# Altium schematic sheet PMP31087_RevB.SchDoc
size 431 x 279 mm; Date: Not shown in title block; ApprovedBy: Not shown in title block; CheckedBy: Not shown in title block; Author: Not shown in title block; CompanyName: Not shown in title block; Engineer: Not shown in title block; Organization: Not shown in title block; Address1: Not shown in title block; Address2: Not shown in title block; Address3: Not shown in title block; Address4: Not shown in title block; DocumentNumber: 1; Revision: Use project parameter SCH_Rev; SheetNumber: 1; SheetTotal: 1; PageSetup: Record=PageOptions¦CenterHorizontal=True¦CenterVertical=True¦PrintScale=1.00¦XCorrection=1.00¦YCorrection=1.00¦PrintKind=0¦BorderSize=5000000¦LeftOffset=0¦BottomOffset=0¦Orientation=2¦PaperLength=1000¦PaperWidth=1000¦Scale=100¦PaperSource=15¦PrintQuality=600¦MediaType=1¦DitherType=10¦PaperKind=Letter¦PrintScaleMode=1
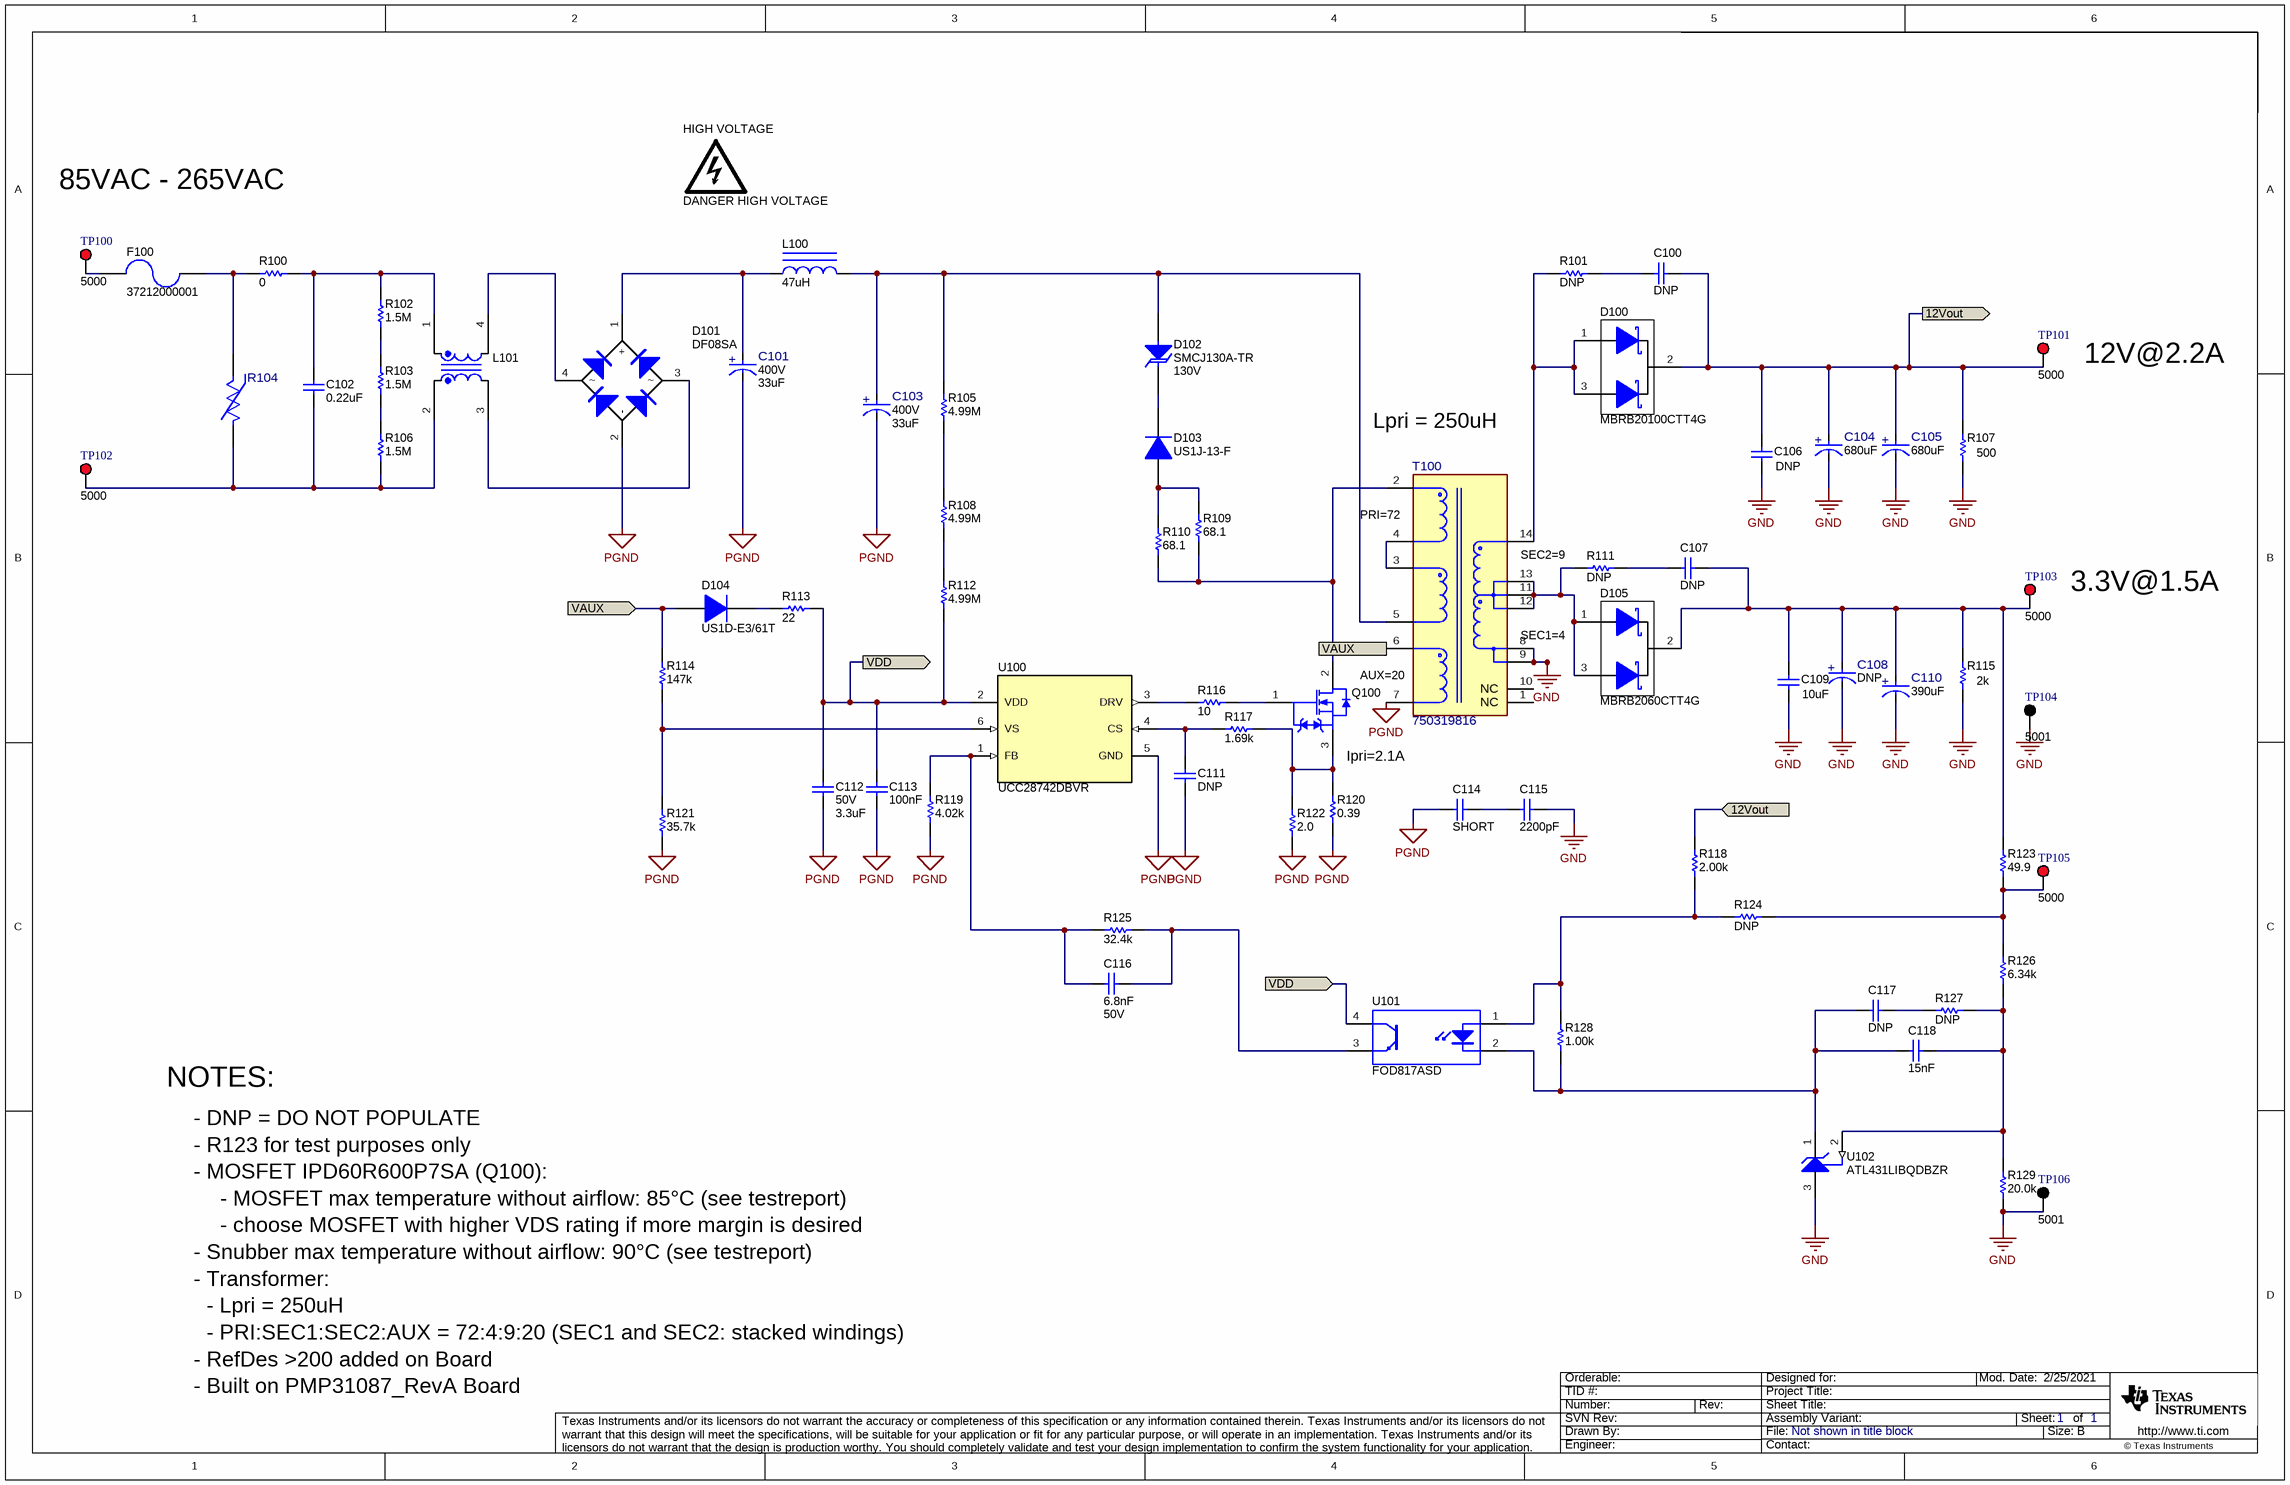
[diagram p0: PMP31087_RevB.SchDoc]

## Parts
C100  Cap_F: DNP  [0805_HV]  (hidden comment: GRM21AR72E102KW01D)
C101  VDC_V: 400V  ValueDisplayed: 33uF  [FP-860241381004_RADIAL-MFG]  (hidden comment: 860241381004)
C102  ValueDisplayed: 0.22uF  [WCAP-FTX2_1800x600x1150]  (hidden comment: 890324025027CS)
C103  VDC_V: 400V  ValueDisplayed: 33uF  [FP-860241381004_RADIAL-MFG]  (hidden comment: 860241381004)
C104  ValueDisplayed: 680uF  [FP-25ZL680MEFC10X20_RADIAL-MFG]  (hidden comment: 25ZL680MEFC10X20)
C105  ValueDisplayed: 680uF  [FP-25ZL680MEFC10X20_RADIAL-MFG]  (hidden comment: 25ZL680MEFC10X20)
C106  ValueDisplayed: DNP  [1210_200]  (hidden comment: GRM32RR71H105KA01L)
C107  Cap_F: DNP  [0805_HV]  (hidden comment: GRM21AR72E102KW01D)
C108  DNP  [FP-APXJ100ARA391MFA0G_SMD2-MFG]
C109  ValueDisplayed: 10uF  [1206]  (hidden comment: C3216X7R1A106M085AC)
C110  ValueDisplayed: 390uF  [FP-APXJ100ARA391MFA0G_SMD2-MFG]  (hidden comment: APXJ100ARA391MFA0G)
C111  Cap_F: DNP  [0603]
C112  VDC_V: 50V  ValueDisplayed: 3.3uF  [1206_190]  (hidden comment: C3216X7R1H335K160AC)
C113  Cap_F: 100nF  [0603]  (hidden comment: C1608X7R1H104K080AA)
C114  ValueDisplayed: SHORT  [C900_9x13]
C115  ValueDisplayed: 2200pF  [C900_9x13]  (hidden comment: C921U222MVVDBA7317)
C116  Cap_F: 6.8nF  VDC_V: 50V  [0603]  (hidden comment: C0603C682K5RACTU)
C117  Cap_F: DNP  [0603]
C118  Cap_F: 15nF  [0603]  (hidden comment: GRM188R71H153KA01D)
D100  MBRB20100CTT4G  [DDPAK]
D101  DF08SA  [DF-S]
D102  SMCJ130A-TR  value 130V  [SMC]
D103  US1J-13-F  [SMA]
D104  US1D-E3/61T  [SMA]
D105  MBRB2060CTT4G  [DDPAK]
F100  37212000001  [FUSE_372]
HIGH_VOLTAGE  DANGER HIGH VOLTAGE  [IEC_HighVoltage_Small]  (no BOM)
L100  ValueDisplayed: 47uH  [WE-TI_8075_STU]  (hidden comment: 744732470)
L101  744823220  [WE-CMB_M]  (value not drawn)
Q100  IPD60R600P7SAUMA1  [DPAK]  (value not drawn)
R100  ValueDisplayed: 0  [1210]  (hidden comment: CRCW12100000Z0EAHP)
R101  ValueDisplayed: DNP  [1206]  (hidden comment: CRCW120610R0FKEA)
R102  ValueDisplayed: 1.5M  [1206]  (hidden comment: CRCW12061M50JNEA)
R103  ValueDisplayed: 1.5M  [1206]  (hidden comment: CRCW12061M50JNEA)
R104  B72210S2271K101  [FP-B72210S2271K101_RADIAL-MFG]  (value not drawn)
R105  ValueDisplayed: 4.99M  [0603]  (hidden comment: CRCW06034M99FKEA)
R106  ValueDisplayed: 1.5M  [1206]  (hidden comment: CRCW12061M50JNEA)
R107  value 500  [1206]  (hidden comment: Used in BOM report)
R108  ValueDisplayed: 4.99M  [0603]  (hidden comment: CRCW06034M99FKEA)
R109  ValueDisplayed: 68.1  [1206]  (hidden comment: CRCW120668R1FKEA)
R110  ValueDisplayed: 68.1  [1206]  (hidden comment: CRCW120668R1FKEA)
R111  ValueDisplayed: DNP  [1206]  (hidden comment: CRCW120610R0FKEA)
R112  ValueDisplayed: 4.99M  [0603]  (hidden comment: CRCW06034M99FKEA)
R113  ValueDisplayed: 22  [1206]  (hidden comment: CRCW120622R0JNEA)
R114  ValueDisplayed: 147k  [0603]  (hidden comment: CRCW0603147KFKEA)
R115  value 2k  [1206]  (hidden comment: Used in BOM report)
R116  ValueDisplayed: 10  [0805_HV]  (hidden comment: CRCW080510R0JNEA)
R117  ValueDisplayed: 1.69k  [0603]  (hidden comment: CRCW06031K69FKEA)
R118  ValueDisplayed: 2.00k  [0805_HV]  (hidden comment: CRCW08052K00FKEA)
R119  ValueDisplayed: 4.02k  [0603]  (hidden comment: CRCW06034K02FKEA)
R120  ValueDisplayed: 0.39  [1206]  (hidden comment: ERJ-8RQFR39V)
R121  ValueDisplayed: 35.7k  [0603]  (hidden comment: CRCW060335K7FKEA)
R122  ValueDisplayed: 2.0  [0805_HV]  (hidden comment: ERJ-6GEYJ2R0V)
R123  ValueDisplayed: 49.9  [0603]  (hidden comment: CRCW060349R9FKEA)
R124  ValueDisplayed: DNP  [0603]  (hidden comment: CRCW06031K00FKEA)
R125  ValueDisplayed: 32.4k  [0603]  (hidden comment: CRCW060332K4FKEA)
R126  ValueDisplayed: 6.34k  [0603]  (hidden comment: RC0603FR-076K34L)
R127  ValueDisplayed: DNP  [0603]  (hidden comment: CRCW06034K02FKEA)
R128  ValueDisplayed: 1.00k  [0603]  (hidden comment: CRCW06031K00FKEA)
R129  ValueDisplayed: 20.0k  [0603]  (hidden comment: CRCW060320K0FKEA)
T100  750319816  [FP-750319816_PTH_TRANSFORMER_32MM25_27MM05-MFG]
TP100  5000  [Keystone5000]
TP101  5000  [Keystone5000]
TP102  5000  [Keystone5000]
TP103  5000  [Keystone5000]
TP104  5001  [Keystone5001]
TP105  5000  [Keystone5000]
TP106  5001  [Keystone5001]
U100  UCC28742DBVR  [DBV0006A_N]
U101  FOD817ASD  [N04C]
U102  ATL431LIBQDBZR  [DBZ0003A_N]

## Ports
12Vout (in), 12Vout (out), VAUX (in), VAUX (out), VDD (in), VDD (out)

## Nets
GND: C104.1(CATHODE) C105.1(CATHODE) C106.2 C108.1(CATHODE) C109.2 C110.1(CATHODE) C115.1 R107.1 R115.1 R129.1 T100.8 T100.9 TP104.1 TP106.1 U102.3(ANODE)
PGND: C101.1(CATHODE) C103.1(CATHODE) C111.2 C112.2 C113.2 C114.2 D101.2(-) R119.1 R120.1 R121.1 R122.1 T100.7 U100.5(GND)
12Vout: C100.1 C104.2(ANODE) C105.2(ANODE) C106.1 D100.2(K) R107.2 R118.2 TP101.1 ; port 12Vout
VAUX: D104.2(A) R114.2 T100.6 ; port VAUX
VDD: C112.1 C113.1 R112.1 R113.2 U100.2(VDD) U101.4(C) ; port VDD
NetC100_2: C100.2 R101.2
NetC101_2: C101.2(ANODE) D101.1(+) L100.1
NetC102_1: C102.1 L101.1 R100.2 R102.2
NetC102_2: C102.2 L101.2 R104.1 R106.1 TP102.1
NetC103_2: C103.2(ANODE) D102.2(A) L100.2 R105.2 T100.5
NetC107_1: C107.1 C108.2(ANODE) C109.1 C110.2(ANODE) D105.2(K) R115.2 R123.2 TP103.1
NetC107_2: C107.2 R111.2
NetC111_1: C111.1 R117.1 U100.4(CS)
NetC114_1: C114.1 C115.2
NetC116_1: C116.1 R125.2 U101.3(E)
NetC116_2: C116.2 R119.2 R125.1 U100.1(FB)
NetC117_1: C117.1 C118.2 R128.1 U101.2(K) U102.1(CATHODE)
NetC117_2: C117.2 R127.2
NetC118_1: C118.1 R126.1 R127.1 R129.2 U102.2(REF)
NetD100_1: D100.1(A) D100.3(A) R101.1 T100.14
NetD101_3: D101.3 L101.3
NetD101_4: D101.4 L101.4
NetD102_1: D102.1(K) D103.1(K)
NetD103_2: D103.2(A) R109.2 R110.2
NetD104_1: D104.1(K) R113.1
NetD105_1: D105.1(A) D105.3(A) R111.1 T100.11 T100.12 T100.13
NetF100_1: F100.1 R100.1 R104.2
NetF100_2: F100.2 TP100.1
NetQ100_1: Q100.1(G) R116.2
NetQ100_2: Q100.2(D) R109.1 R110.1 T100.2
NetQ100_3: Q100.3(S) R117.2 R120.2 R122.2
NetR102_1: R102.1 R103.2
NetR103_1: R103.1 R106.2
NetR105_1: R105.1 R108.2
NetR108_1: R108.1 R112.2
NetR114_1: R114.1 R121.2 U100.6(VS)
NetR116_1: R116.1 U100.3(DRV)
NetR118_1: R118.1 R124.1 R128.2 U101.1(A)
NetR123_1: R123.1 R124.2 R126.2 TP105.1
NetT100_3: T100.3 T100.4

Not connected (* = marked no-connect by the designer): T100 1(NC) 10(NC)

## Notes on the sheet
- 85VAC - 265VAC
- (near TP101) 12V@2.2A
- Lpri = 250uH
- (near T100) PRI=72
- (near T100) SEC2=9
- (near T100) SEC1=4
- (near TP103) 3.3V@1.5A
- AUX=20
- Ipri=2.1A
- NOTES:
- - DNP = DO NOT POPULATE
- - R123 for test purposes only
- - MOSFET IPD60R600P7SA (Q100):
- - choose MOSFET with higher VDS rating if more margin is desired
- - MOSFET max temperature without airflow: 85°C (see testreport)
- - Transformer:
- - Snubber max temperature without airflow: 90°C (see testreport)
- - Lpri = 250uH
- - RefDes >200 added on Board
- - PRI:SEC1:SEC2:AUX = 72:4:9:20 (SEC1 and SEC2: stacked windings)
- - Built on PMP31087_RevA Board

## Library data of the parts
C100 C107 = CMP-0008251-1: CAP, CERM, 1000 pF, 250 V, +/- 10%, X7R, 0805; Manufacturer: MuRata; TaMin_C: -55°C; Polarized: N; SizeAreaWB_mm2: 6.75; Value1: Unknown; U/M: EA; Value: 1000pF; TaMax_C: 125°C; SizeZ_mm: 1.45; SizeX_mm: 2; SizeY_mm: 1.25; Cap_Case: 0805; Value2: 250V; SizeArea_mm2: 2.5; AEC Category: Q200
C101 C103 = CMP-0093307-1: 33 µF 400 V Aluminum Electrolytic Capacitors Radial, Can - 10000 Hrs @ 105°C; Manufacturer: Wurth Electronics; Value: 33µF; Tolerance_%: 20%; SizeZ_mm: 23mm; Leakage Current: 628uA; Life: 10000Hours; AEC Qualified: No; IRMS_A: 870mA
C102 = CMP-0012315-3: CAP, Film, 0.22 uF, 275 V, +/- 10%, TH; Manufacturer: Wurth Elektronik; TaMin_C: -40°C; Polarized: N; Value1: Unknown; Value: 0.22uF; TaMax_C: 105°C; Cap_Case: 18x11.5x6mm; Value2: 275V; Cap_F: 220nF; AEC Category: Q200
C104 C105 = CMP-0092158-1: Aluminum Electrolytic Capacitors Radial, Can - 4000 Hrs @ 105°C 680UF 25V; Manufacturer: Rubycon; Dissipation Factor: 14%; Value: 680µF; Leakage Current: 170uA; Life: 4000Hours; AEC Qualified: No; IRMS_A: 1.82A; Tolerance_%: 20%; SizeZ_mm: 22mm
C106 = CMP-0009251-1: CAP, CERM, 1 uF, +/- 10%, X7R, 1210; Manufacturer: MuRata; TaMin_C: -55°C; ESR_ohm: 3m; Polarized: N; SizeAreaWB_mm2: 14.7; Value1: 0.003 ohm; U/M: EA; Value: DNP; TaMax_C: 125°C; SizeZ_mm: 2; SizeX_mm: 3.2; SizeY_mm: 2.5; Cap_Case: 1210; SizeArea_mm2: 8
C108 = CMP-0092160-1: Capacitors Radial; SizeZ_mm: 10mm; Cap_F: 390µF; AEC Qualified: No; Leakage Current: 1950uA; Life: 15000Hours; Tolerance_%: 20%; Dissipation Factor: 12%; IRMS_A: 4A; Esr: 13m
C109 = CMP-0008688-1: CAP, CERM, 10 uF, 10 V, +/- 10%, X7R, 1206; Manufacturer: TDK; TaMin_C: -55°C; Polarized: N; SizeAreaWB_mm2: 10.92; Value1: Unknown; U/M: EA; Value: 10uF; TaMax_C: 125°C; SizeZ_mm: 1.35; SizeX_mm: 3.2; SizeY_mm: 1.6; Value2: 10V; SizeArea_mm2: 5.12; Cap_F: 10µF; AEC Category: Q200
C110 = CMP-0092160-1: Aluminum - Polymer Capacitors Radial, Can - SMD 13mOhm 15000 Hrs @ 105°C; Manufacturer: United Chemi-Con; SizeZ_mm: 10mm; Cap_F: 390µF; AEC Qualified: No; Leakage Current: 1950uA; Life: 15000Hours; Tolerance_%: 20%; VDC_V: 10V; Value: 390µF; Dissipation Factor: 12%; IRMS_A: 4A; Esr: 13m
C111 C117 = CMP-0007465-1: CAP, CERM, +/- 10%, X7R, 0603; Manufacturer: MuRata; TaMin_C: -55°C; Polarized: N; SizeAreaWB_mm2: 4.68; Value1: Unknown; U/M: EA; Value: DNP; TaMax_C: 125°C; SizeZ_mm: 1; SizeX_mm: 1.6; SizeY_mm: 0.8; SizeArea_mm2: 1.28
C112 = CMP-0008700-1: CAP, CERM, 3.3 uF, 50 V, +/- 10%, X7R, 1206_190; Manufacturer: TDK; TaMin_C: -55°C; Polarized: N; SizeAreaWB_mm2: 10.92; Value1: Unknown; U/M: EA; Value: 3.3uF; TaMax_C: 125°C; SizeZ_mm: 1.9; SizeX_mm: 3.2; SizeY_mm: 1.6; Cap_Case: 1206; SizeArea_mm2: 5.12; Cap_F: 3.3µF; AEC Category: Q200
C113 = CMP-0007044-1: CAP, CERM, 0.1 uF, 50 V, +/- 10%, X7R, 0603; Manufacturer: TDK; TaMin_C: -55°C; ESR_ohm: 29.6m; Polarized: N; SizeAreaWB_mm2: 4.68; Value1: 0.0296 ohm; U/M: EA; Value: 0.1uF; TaMax_C: 125°C; SizeZ_mm: 1; SizeX_mm: 1.6; SizeY_mm: 0.8; Value2: 50V; SizeArea_mm2: 1.28; IRMS_A: 971.99mA; AEC Category: Q200
C114 = CMP-0078358-1: CAP, CERM, 2200 pF, X1 400 VAC/Y1 400 VAC, +/- 20%, Y5V, D9xL13mm; Manufacturer: Kemet; SizeAreaWB_mm2: 121; SizeArea_mm2: 81; AEC Qualified: N; AEC Category: Q200; Value: 2200pF; TaMax_C: 125°C; SizeZ_mm: 13; TaMin_C: -40°C; SizeY_mm: 9; U/M: EA; AC_Safety: X1Y1; Cap_Case: 9x13mm
C115 = CMP-0078358-1: CAP, CERM, 2200 pF, X1 400 VAC/Y1 400 VAC, +/- 20%, Y5V, D9xL13mm; Manufacturer: Kemet; Cap_F: 2.2nF; SizeAreaWB_mm2: 121; VAC_X: 400V; SizeArea_mm2: 81; AEC Qualified: N; AEC Category: Q200; Value: 2200pF; TaMax_C: 125°C; SizeZ_mm: 13; TaMin_C: -40°C; SizeY_mm: 9; U/M: EA; AC_Safety: X1Y1; Cap_Case: 9x13mm
C116 = CMP-0006963-3: CAP, CERM, 6800 pF, 50 V, +/- 10%, X7R, 0603; Manufacturer: Kemet; TaMin_C: -55°C; Polarized: N; SizeAreaWB_mm2: 4.68; Value1: Unknown; U/M: EA; Value: 6800pF; TaMax_C: 125°C; SizeZ_mm: 1; SizeX_mm: 1.6; SizeY_mm: 0.8; SizeArea_mm2: 1.28; AEC Category: Q200
C118 = CMP-0007438-4: CAP, CERM, 0.015 uF, 50 V, +/- 10%, X7R, 0603; Manufacturer: MuRata; TaMin_C: -55°C; Polarized: N; SizeAreaWB_mm2: 4.68; Value1: Unknown; U/M: EA; TaMax_C: 125°C; SizeZ_mm: 1; SizeX_mm: 1.6; SizeY_mm: 0.8; Value2: 50V; SizeArea_mm2: 1.28; AEC Category: Q200
D100 = CMP-0028499-3: Diode, Schottky, 100 V, 20 A, DDPAK; Manufacturer: ON Semiconductor; SizeY_mm: 10.16; Io_A: 20A; TJmax_C: 150°C; Vf_V: 950mV; AEC Category: Q101; Green_Lifecycle: Not Set; Vr_V: 100V; SizeX_mm: 15.245; Green_REACh: Incomplete; SizeAreaWB_mm2: 209.6992; Value: 100V; RJC_CperW: 2; SizeArea_mm2: 154.8892; Value2: 0.95V; SizeZ_mm: 4.445
D101 = CMP-0029205-3: Diode, Switching-Bridge, 800 V, 1 A, DF-S; Manufacturer: Vishay-Semiconductor; SizeAreaWB_mm2: 98.794; Value1: 1A; Value2: 1.1V; SizeArea_mm2: 62.974; Vr_V: 800V; Value: 800V; AEC Category: Q101; SizeZ_mm: 3.4; TJmax_C: 150°C; Green_Lifecycle: Not Set; SizeX_mm: 7.4; RJC_CperW: 15; Green_REACh: Incomplete; SizeY_mm: 8.51
D102 = CMP-0085439-1: Diode, TVS, Uni, 130 V, 209 Vc, 1500 W, 7.5 A, SMC; Manufacturer: STMicroelectronics; Ppk: 1.5kW; SizeY_mm: 6.22; SizeAreaWB_mm2: 83.2686; Vbr_Min: 144V; SizeZ_mm: 2.62; Ipp: 7.5A; AEC Qualified: N; AEC Category: Q101; SizeX_mm: 8.13; Vc: 209V; SizeArea_mm2: 50.5686; RJA_CperW: 90
D103 = CMP-0077027-2: Diode, Ultrafast, 600 V, 1 A, SMA; Manufacturer: Diodes Inc.; Value: 600V; TJmax_C: 150°C; Value1: 1A; Value2: 1.7V; SizeY_mm: 2.92; Green_REACh: Passed; Green_Lifecycle: Active; SizeX_mm: 5.59; AEC Category: Q101; SizeAreaWB_mm2: 37.3428; SizeZ_mm: 2.87; SizeArea_mm2: 16.3228
D104 = CMP-0029189-1: Diode, Ultrafast, 200 V, 1 A, AEC-Q101, SMA; Manufacturer: Vishay-Semiconductor; Io_A: 1A; SizeAreaWB_mm2: 37.3428; Vr_V: 200V; TJmax_C: 150°C; U/M: EA; Value: 200V; SizeZ_mm: 2.87; SizeX_mm: 5.59; SizeY_mm: 2.92; Vf_V: 1V; SizeArea_mm2: 16.3228; AEC Qualified: Y; AEC Category: Q101
D105 = CMP-0028501-3: Diode, Schottky, 60 V, 20 A, DDPAK; Manufacturer: ON Semiconductor; Value1: 20A; Vr_V: 60V; SizeArea_mm2: 154.8892; Value2: 0.95V; Green_Lifecycle: Not Set; SizeAreaWB_mm2: 209.6992; SizeX_mm: 15.245; SizeY_mm: 10.16; Green_REACh: Incomplete; TJmax_C: 150°C; Value: 60V; SizeZ_mm: 4.445; Vf_V: 950mV; RJC_CperW: 2; AEC Category: Q101
F100 = CMP-0003555-1: Fuse, 2 A, 250VAC/VDC, TH; Manufacturer: Littelfuse; Irating_A: 2A; VAC_V: 250V
HIGH_VOLTAGE = CMP-0074835-1: IEC 61010-1 High Voltage Warning; SymbolCreator: a0412235
L100 = CMP-0064737-2: Inductor, Unshielded Drum Core, Metal Composite, 47 uH,; Manufacturer: Wurth Elektronik; PartNumber: 744732681; SizeAreaWB_mm2: 132.25; DCR_ohm: 2.2; Value: 47uH; SizeZ_mm: 8; SizeX_mm: 9.5; SizeArea_mm2: 90.25; Ind_H: 47µH; AEC Qualified: N; AEC Category: Q200
L101 = CMP-0013122-2: Coupled inductor, 20 mH, 1.5 A, 0.27 ohm, TH; Manufacturer: Wurth Elektronik; SizeAreaWB_mm2: 513; DCR_ohm: 0.27; Value: 20mH; SizeZ_mm: 26.5; SizeX_mm: 25; SizeY_mm: 17; SizeArea_mm2: 425
Q100 = CMP-0081319-2: MOSFET, N-CH, 600 V, 6 A, DPAK; Alternate Manufacturer: None; Manufacturer: Infineon Technologies; ChMode: Enhancement; IdsMax_A: 6A; Value2: 9 nC; VdsMax_V: 600V; AEC Qualified: N; Vgs_V: 20V; QgTyp_nC: 9; Value1: ? ohm; SizeX_mm: 9.91; SizeZ_mm: 2.29; SizeY_mm: 6.54; Value: 600V; SizeAreaWB_mm2: 101.7114; SizeArea_mm2: 64.8114; AEC Category: Q101
R100 = CMP-0015017-1: RES, 0, 1%, 0.75 W, AEC-Q200 Grade 0, 1210; Manufacturer: Vishay-Dale; Power_W: 750mW; TempCo: ppm/C; SizeAreaWB_mm2: 14.7; U/M: EA; Value: 0; SizeX_mm: 3.2; SizeY_mm: 2.5; SizeZ_mm: 1.35; Value2: 0.75W; SizeArea_mm2: 8; AEC Qualified: Y; AEC Category: Q200
R101 R111 = CMP-0016583-1: RES, 10.0, 1%, 0.25 W, 1206; Manufacturer: Vishay-Dale; Power_W: 250mW; TempCo: 100 ppm/C; Value_Code: 10R0; U/M: EA; Value: 10.0; EIA_Code: E96; Res_ohm: 10; SizeX_mm: 3.2; SizeY_mm: 1.6; SizeZ_mm: 1.35; Value2: 0.25W; SizeArea_mm2: 5.12; VDC_V: 200V; AEC Category: Q200
R102 R103 R106 = CMP-0018614-2: RES, 1.5 M, 5%, 0.25 W, 1206; Manufacturer: Vishay-Dale; Power_W: 250mW; TempCo: 200 ppm/C; Value_Code: 1M50; U/M: EA; Value: 1.5Meg; EIA_Code: E24; SizeX_mm: 3.2; SizeY_mm: 1.6; SizeZ_mm: 1.35; Value2: 0.25W; SizeArea_mm2: 5.12; VDC_V: 200V; AEC Category: Q200
R104 = CMP-0090587-1: VARISTOR 430V 3.5KA DISC 10MM; Manufacturer: EPCOS; AEC Qualified: No; Voltage Tolerance: 10%; Cap_F: 220pF; Vc: 25A; Clamping Voltage: 710V; SizeZ_mm: 14.5mm; VDC_V: 350V
R105 R108 R112 = CMP-0022468-2: RES, 4.99 M, 1%, 0.1 W, 0603; Manufacturer: Vishay-Dale; Power_W: 100mW; TempCo: 100 ppm/C; Value_Code: 4M99; U/M: EA; Value: 4.99Meg; EIA_Code: E96; SizeX_mm: 1.6; SizeY_mm: 0.8; SizeZ_mm: 1; Value2: 0.1W; SizeArea_mm2: 1.28; VDC_V: 75V; AEC Category: Q200
R107 R115 = Resistor: RES, xxx ohm, x%, xW, [PackageReference]; U/M: EA
R109 R110 = CMP-0017122-3: RES, 68.1, 1%, 0.25 W, AEC-Q200 Grade 0, 1206; Manufacturer: Vishay-Dale; Power_W: 250mW; TempCo: 100 ppm/C; Value_Code: 68R1; Value: 68.1; EIA_Code: E96; SizeX_mm: 3.2; SizeY_mm: 1.6; SizeZ_mm: 1.35; Value2: 0.25W; SizeArea_mm2: 5.12; AEC Qualified: Y; VDC_V: 200V; AEC Category: Q200; AEC Grade: 0
R113 = CMP-0018631-3: RES, 22, 5%, 0.25 W, AEC-Q200 Grade 0, 1206; Manufacturer: Vishay-Dale; Power_W: 250mW; TempCo: 200 ppm/C; Value_Code: 22R0; Value: 22; EIA_Code: E24; SizeX_mm: 3.2; SizeY_mm: 1.6; SizeZ_mm: 1.35; Value2: 0.25W; SizeArea_mm2: 5.12; AEC Qualified: Y; VDC_V: 200V; AEC Category: Q200; AEC Grade: 0
R114 = CMP-0022052-3: RES, 147 k, 1%, 0.1 W, 0603; Manufacturer: Vishay-Dale; Power_W: 100mW; TempCo: 100 ppm/C; U/M: EA; Value: 147k; EIA_Code: E96; SizeX_mm: 1.6; SizeY_mm: 0.8; SizeZ_mm: 1; Value2: 0.1W; SizeArea_mm2: 1.28; VDC_V: 75V; AEC Category: Q200
R116 = CMP-0020448-1: RES, 10, 5%, 0.125 W, 0805; Manufacturer: Vishay-Dale; Power_W: 125mW; TempCo: 200 ppm/C; Value_Code: 10R0; U/M: EA; Value: 10; EIA_Code: E24; SizeX_mm: 2; SizeY_mm: 1.25; SizeZ_mm: 1.45; Value2: 0.125W; SizeArea_mm2: 2.5; VDC_V: 150V; AEC Category: Q200
R117 = CMP-0022131-2: RES, 1.69 k, 1%, 0.1 W, 0603; Manufacturer: Vishay-Dale; Power_W: 100mW; TempCo: 100 ppm/C; Value_Code: 1k69; U/M: EA; Value: 1.69k; EIA_Code: E96; SizeX_mm: 1.6; SizeY_mm: 0.8; SizeZ_mm: 1; Value2: 0.1W; SizeArea_mm2: 1.28; VDC_V: 75V; AEC Category: Q200
R118 = CMP-0021106-1: RES, 2.00 k, 1%, 0.125 W, 0805; Manufacturer: Vishay-Dale; Power_W: 125mW; TempCo: 100 ppm/C; Value_Code: 2k00; U/M: EA; Value: 2.00k; EIA_Code: E96; Res_ohm: 2k; SizeX_mm: 2; SizeY_mm: 1.25; SizeZ_mm: 1.45; Value2: 0.125W; SizeArea_mm2: 2.5; VDC_V: 150V; AEC Category: Q200
R119 = CMP-0022449-1: RES, 4.02 k, 1%, 0.1 W, 0603; Manufacturer: Vishay-Dale; Power_W: 100mW; TempCo: 100 ppm/C; Value_Code: 4k02; U/M: EA; Value: 4.02k; EIA_Code: E96; SizeX_mm: 1.6; SizeY_mm: 0.8; SizeZ_mm: 1; Value2: 0.1W; SizeArea_mm2: 1.28; VDC_V: 75V; AEC Category: Q200
R120 = CMP-0017789-2: RES, 0.39, 1%, 0.25 W, 1206; Manufacturer: Panasonic; Power_W: 250mW; TempCo: 250 ppm/C; Value_Code: R390; U/M: EA; Value: 0.39; EIA_Code: E96; SizeX_mm: 3.2; SizeY_mm: 1.6; SizeZ_mm: 1.35; Value2: 0.25W; SizeArea_mm2: 5.12; AEC Category: Q200
R121 = CMP-0022352-2: RES, 35.7 k, 1%, 0.1 W, 0603; Manufacturer: Vishay-Dale; Power_W: 100mW; TempCo: 100 ppm/C; Value_Code: 35k7; U/M: EA; Value: 35.7k; EIA_Code: E96; SizeX_mm: 1.6; SizeY_mm: 0.8; SizeZ_mm: 1; Value2: 0.1W; SizeArea_mm2: 1.28; VDC_V: 75V; AEC Category: Q200
R122 = CMP-0020692-2: RES, 2.0, 5%, 0.125 W, 0805; Manufacturer: Panasonic; Power_W: 125mW; TempCo: 600 ppm/C; Value_Code: 2R00; U/M: EA; Value: 2.0; EIA_Code: E24; Res_ohm: 2; SizeY_mm: 1.25; SizeZ_mm: 1.45; Value2: 0.125W; SizeArea_mm2: 2.5; VDC_V: 150V; AEC Category: Q200
R123 = CMP-0022448-2: RES, 49.9, 1%, 0.1 W, 0603; Manufacturer: Vishay-Dale; Power_W: 100mW; TempCo: 100 ppm/C; Value_Code: 49R9; U/M: EA; Value: 49.9; EIA_Code: E96; SizeX_mm: 1.6; SizeY_mm: 0.8; SizeZ_mm: 1; Value2: 0.1W; SizeArea_mm2: 1.28; VDC_V: 75V; AEC Category: Q200
R124 R128 = CMP-0022109-4: RES, 1.00 k, 1%, 0.1 W, 0603; Manufacturer: Vishay-Dale; Power_W: 100mW; TempCo: 100 ppm/C; Value_Code: 1k00; U/M: EA; Value: 1.00k; EIA_Code: E96; Res_ohm: 1k; SizeX_mm: 1.6; SizeY_mm: 0.8; SizeZ_mm: 1; Value2: 0.1W; SizeArea_mm2: 1.28; VDC_V: 75V; AEC Category: Q200
R125 = CMP-0022334-3: RES, 32.4 k, 1%, 0.1 W, 0603; Manufacturer: Vishay-Dale; Power_W: 100mW; TempCo: 100 ppm/C; Value_Code: 32k4; U/M: EA; Value: 32.4k; EIA_Code: E96; SizeX_mm: 1.6; SizeY_mm: 0.8; SizeZ_mm: 1; Value2: 0.1W; SizeArea_mm2: 1.28; VDC_V: 75V; AEC Category: Q200
R126 = CMP-0023249-5: RES, 6.34 k, 1%, 0.1 W, 0603; Manufacturer: Yageo; EIA_Code: E96; SizeAreaWB_mm2: 4.68; Power_W: 100mW; TempCo: 100 ppm/C; Value_Code: 6k34; Value: 6.34k; SizeX_mm: 1.6; SizeY_mm: 0.8; SizeZ_mm: 1; Value2: 0.1W; SizeArea_mm2: 1.28; AEC Qualified: N; VDC_V: 75V; AEC Category: Q200
R127 = CMP-0022449-1: RES, 1%, 0.1 W, 0603; Manufacturer: Vishay-Dale; Power_W: 100mW; TempCo: 100 ppm/C; U/M: EA; Value: DNP; EIA_Code: E96; SizeX_mm: 1.6; SizeY_mm: 0.8; SizeZ_mm: 1; Value2: 0.1W; SizeArea_mm2: 1.28; VDC_V: 75V
R129 = CMP-0022204-3: RES, 20.0 k, 1%, 0.1 W, 0603; Manufacturer: Vishay-Dale; Power_W: 100mW; TempCo: 100 ppm/C; Value_Code: 20k0; U/M: EA; Value: 20.0k; EIA_Code: E96; Res_ohm: 20k; SizeX_mm: 1.6; SizeY_mm: 0.8; SizeZ_mm: 1; Value2: 0.1W; SizeArea_mm2: 1.28; VDC_V: 75V; AEC Category: Q200
T100 = CMP-0093376-1: TRANSFORMER; Manufacturer: Wurth Electronics; SizeZ_mm: 22.86mm; DCR_ohm: 0.87; Rsec1_ohm: 20m; Frequency_Fixed: 70kHz; Voltage_Isolation_Vrms: 3kV; Ind_H: 225µH; AEC Qualified: No; Ns1toNp: 5.54:1
TP100-TP103 TP105 = CMP-0055137-1: Test Point, Miniature, Red, TH; Manufacturer: Keystone; CNHeader: FALSE; Green_Lifecycle: Active; Green_REACh: Passed; ContactFinish: Silver; CT: TRUE
TP104 TP106 = CMP-0055138-1: Test Point, Miniature, Black, TH; Manufacturer: Keystone; CNHeader: FALSE; Green_Lifecycle: Active; Green_REACh: Passed; ContactFinish: Silver; CT: TRUE
U100 = CMP-0078369-1: High-Efficiency Low-Cost Flyback Controller with Secondary-Side Regulation, DBV0006A (SOT-23-6); Manufacturer: Texas Instruments; SizeZ_mm: 1.45; SizeX_mm: 2.8; SizeY_mm: 2.9; AEC Category: Q200; AEC Qualified: N; SizeArea_mm2: 8.12; CompType: IC; SizeAreaWB_mm2: 14.82
U101 = CMP-0006181-3: Optocoupler, 5 kV, 80-160% CTR, SMT; Manufacturer: Fairchild Semiconductor; CTR (Max): 160%; CTR (Min): 80%; Voltage_Isolation_Vrms: 5kV
U102 = CMP-0084731-1: High Bandwidth Low-Iq Programmable Shunt Regulator, DBZ0003A (SOT-23-3); Manufacturer: Texas Instruments; CompType: IC; SizeX_mm: 2.5; AEC Category: Q200; SizeY_mm: 3; SizeArea_mm2: 7.5; AEC Qualified: N; SizeZ_mm: 1.12; SizeAreaWB_mm2: 14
